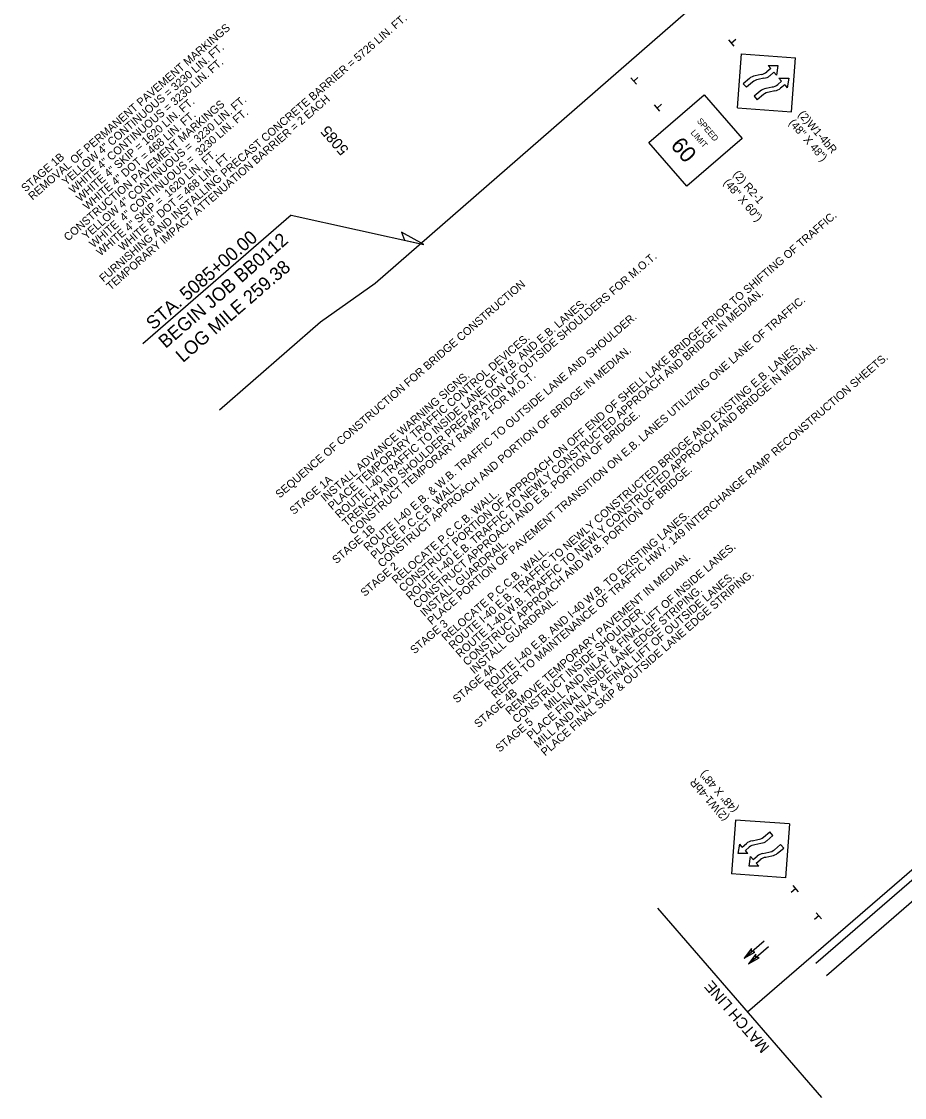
# Model space of a CAD drawing. Extents: x 259983 to 267998, y 211467 to 219827.
# Drawn here: x 259983 to 261307, y 216506 to 218119 of the extents above; entities that cross this region are included whole.
import ezdxf

# ---------------------------------------------------------------- set-up
doc = ezdxf.new("R2010")
doc.units = 0
for name, color, linetype in [('Default', 7, 'Continuous'), ('Level 24', 7, 'Continuous'), ('Level 43', 7, 'Continuous'), ('Level 58', 7, 'Continuous'), ('Level 59', 7, 'Continuous'), ('R-W - CofA', 7, 'Continuous'), ('R_MOT', 7, 'Continuous'), ('R_MOT STAGE 1', 7, 'Continuous'), ('R_MOT STAGE 2', 7, 'Continuous'), ('ROAD', 7, 'Continuous'), ('STATIONING1', 7, 'Continuous')]:
    doc.layers.add(name, color=color, linetype=linetype)

msp = doc.modelspace()

# ---------------------------------------------------------------- linework, layer by layer
at = {"layer": 'Level 24'}
for points in [[(260387.1, 217828.4), (260164.4, 217635.7)], [(260387.1, 217828.4), (260585.8, 217784.8)]]:
    msp.add_lwpolyline(points, dxfattribs=at)
at = {"layer": 'Level 43'}
for points in [[(261066, 216714.9), (261096, 216740.8)], [(261072.6, 216706.1), (261102.6, 216732.1)]]:
    msp.add_lwpolyline(points, dxfattribs=at)
at = {"layer": 'Level 58'}
for points in [[(261077.2, 216729.5), (261066, 216714.9), (261082.1, 216723.8), (261077.4, 216724.7)], [(261083.7, 216720.8), (261072.6, 216706.1), (261088.6, 216715.1), (261083.9, 216716)]]:
    msp.add_lwpolyline(points, close=True, dxfattribs=at)
at = {"layer": 'Level 59'}
msp.add_lwpolyline([(260557.1, 217791), (260585.8, 217784.8), (260552.6, 217802.9)], close=True, dxfattribs=at)
at = {"layer": 'R-W - CofA'}
msp.add_lwpolyline([(260279.4, 217536.6), (260430.8, 217668.5), (260512.8, 217726.6), (260994.1, 218146)], dxfattribs=at)
at = {"layer": 'R_MOT'}
for p, q in [((261051, 218082.1), (261043, 218091.4)), ((261047, 218086.7), (261053.5, 218092.3)), ((261056.4, 217989.4), (261062.2, 218070.3)), ((261062.2, 218070.3), (261143, 218064.4)), ((261102, 218052.9), (261116.6, 218053)), ((261102, 218052.9), (261105.9, 218048.4)), ((261116.6, 218053), (261114.5, 218038.5)), ((261137.1, 217983.7), (261143, 218064.4)), ((260904.5, 218025.1), (260896.4, 218034.3)), ((260900.5, 218029.7), (260906.9, 218035.2)), ((261074, 218033.6), (261064.9, 218025.7)), ((261091.7, 218039.4), (261082.6, 218037.3)), ((261095.9, 218033.9), (261087.3, 218031.9)), ((261105.9, 218048.4), (261100.2, 218043.4)), ((261110.6, 218043), (261104.4, 218037.7)), ((261110.6, 218043), (261114.5, 218038.5)), ((261118.3, 218034), (261133, 218034.1)), ((261118.3, 218034), (261122.2, 218029.6)), ((261133, 218034.1), (261130.8, 218019.7)), ((261064.9, 218025.7), (261069.6, 218020.3)), ((261078.7, 218028.2), (261069.6, 218020.3)), ((261108, 218020.6), (261099, 218018.4)), ((261122.2, 218029.6), (261116.5, 218024.6)), ((261126.9, 218024.2), (261120.7, 218018.8)), ((261126.9, 218024.2), (261130.8, 218019.7)), ((261090.4, 218014.7), (261081.2, 218006.8)), ((261081.2, 218006.8), (261085.9, 218001.4)), ((261095, 218009.3), (261085.9, 218001.4)), ((261112.2, 218015.1), (261103.6, 218013)), ((260939.5, 217984.6), (260931.5, 217993.8)), ((260935.5, 217989.2), (260942, 217994.8)), ((261056.4, 217989.4), (261137.1, 217983.7)), ((261053.1, 216921.9), (261047.3, 216841.2)), ((261133.9, 216916.2), (261053.1, 216921.9)), ((261095.3, 216896.3), (261104.4, 216904.2)), ((261109, 216898.8), (261104.4, 216904.2)), ((261133.9, 216916.2), (261128.1, 216835.3)), ((261078.1, 216890.5), (261086.7, 216892.6)), ((261099.9, 216890.9), (261109, 216898.8)), ((261057.3, 216871.5), (261059.5, 216885.9)), ((261071.9, 216871.6), (261057.3, 216871.5)), ((261063.4, 216881.4), (261059.5, 216885.9)), ((261063.4, 216881.4), (261069.5, 216886.8)), ((261068, 216876), (261073.8, 216881)), ((261071.9, 216871.6), (261068, 216876)), ((261082.3, 216885), (261091.3, 216887.2)), ((261094.4, 216871.7), (261103, 216873.7)), ((261111.6, 216877.4), (261120.7, 216885.3)), ((261116.2, 216872), (261125.4, 216879.9)), ((261125.4, 216879.9), (261120.7, 216885.3)), ((261073.6, 216852.6), (261075.8, 216867.1)), ((261079.7, 216862.6), (261075.8, 216867.1)), ((261079.7, 216862.6), (261085.9, 216867.9)), ((261084.4, 216857.2), (261090.1, 216862.2)), ((261088.3, 216852.7), (261084.4, 216857.2)), ((261098.6, 216866.2), (261107.6, 216868.3)), ((261128.1, 216835.3), (261047.3, 216841.2)), ((261088.3, 216852.7), (261073.6, 216852.6)), ((261139.2, 216823.5), (261147.3, 216814.2)), ((261143.2, 216818.9), (261136.8, 216813.3)), ((261178.3, 216778.4), (261171.8, 216772.8)), ((261174.3, 216783), (261182.3, 216773.7))]:
    msp.add_line(p, q, dxfattribs=at)
msp.add_lwpolyline([(261063.1, 217943.5), (260980.3, 217871.9), (260923.4, 217937.6), (261006.3, 218009.2)], close=True, dxfattribs=at)
for centre, major_axis in [((261085.9, 218020.4), (-11.6, 13.4)), ((261088.3, 218056.6), (11.6, -13.4)), ((261092.5, 218050.8), (11.6, -13.4)), ((261090.6, 218015), (-11.6, 13.4)), ((261102.2, 218001.5), (-11.6, 13.4)), ((261104.6, 218037.7), (11.6, -13.4)), ((261108.9, 218032), (11.6, -13.4)), ((261106.9, 217996.1), (-11.6, 13.4)), ((261081.4, 216873.6), (-11.6, 13.4)), ((261083.3, 216909.5), (11.6, -13.4)), ((261088, 216904), (11.6, -13.4)), ((261085.7, 216867.9), (-11.6, 13.4)), ((261097.7, 216854.7), (-11.6, 13.4)), ((261099.6, 216890.6), (11.6, -13.4)), ((261104.4, 216885.2), (11.6, -13.4)), ((261102, 216849), (-11.6, 13.4))]:
    msp.add_ellipse(centre, major_axis=major_axis, ratio=0.9, start_param=5.717125, end_param=6.306311, dxfattribs=at)
at = {"layer": 'R_MOT STAGE 1'}
for p, q in [((261173.7, 216707.1), (261504.2, 216993.2)), ((261189.4, 216688.9), (261519.9, 216975)), ((261182.4, 216506), (260936.7, 216789.8))]:
    msp.add_line(p, q, dxfattribs=at)
at = {"layer": 'R_MOT STAGE 2'}
msp.add_line((261071.3, 216634.3), (261479, 216987.2), dxfattribs=at)

# ---------------------------------------------------------------- texts
at = {"layer": 'Default'}
for s, p in [('REMOVAL OF PERMANENT PAVEMENT MARKINGS', (259999.2, 217850.4)), ('FURNISHING AND INSTALLING PRECAST CONCRETE BARRIER = 5726 LIN. FT.', (260105.6, 217727.5)), (' YELLOW 4" CONTINUOUS = 3230 LIN. FT.', (260046.1, 217869.6)), (' WHITE 4" CONTINUOUS = 3230 LIN. FT.', (260056.8, 217857.3)), ('CONSTRUCTION PAVEMENT MARKINGS', (260052.4, 217789)), (' WHITE 4" SKIP = 1620 LIN. FT.', (260067.4, 217845)), ('     YELLOW 4" CONTINUOUS =  3230 LIN. FT.', (260063, 217776.7)), ('TEMPORARY IMPACT ATTENUATION BARRIER = 2 EACH', (260116.2, 217715.3)), ('     WHITE  4" CONTINUOUS =  3230 LIN. FT.', (260073.7, 217764.4)), (' WHITE 4" DOT = 468 LIN. FT.', (260078, 217832.7)), ('STAGE 1B', (259988.6, 217862.7)), ('     WHITE 4" SKIP =  1620 LIN. FT.', (260084.3, 217752.1)), (' WHITE 8" DOT = 468 LIN. FT.', (260131.2, 217771.3))]:
    msp.add_text(s, height=12, rotation=40.8833, dxfattribs=at).set_placement(p)
at = {"layer": 'Level 24'}
for s, p in [('STA. 5085+00.00', (260180.1, 217655.5)), ('BEGIN JOB BB0112', (260198.7, 217628)), ('LOG MILE 259.38', (260224.6, 217606.7))]:
    msp.add_text(s, height=20, rotation=40.8833, dxfattribs=at).set_placement(p)
at = {"layer": 'R_MOT'}
for s, height, rotation, p in [('(2)W1-4bR', 12, 310.8833, (261146.3, 217979.2)), ('SPEED', 9.05, 310.8555, (260994.8, 217969.4)), ('(48" X 48")', 12, 310.8833, (261132.3, 217966.5)), ('LIMIT', 9.05, 310.8555, (260985.2, 217951.9)), ('60', 24.26, 310.8555, (260954.6, 217932.4)), ('(2) R2-1', 12.13, 310.8555, (261048.8, 217889.5)), ('(48" X 60")', 12.129, 310.8555, (261034.3, 217877)), ('(2)W1-4bR', 12, 130.8833, (261044, 216926.3)), ('(48" X 48")', 12, 130.8833, (261058, 216939.1))]:
    msp.add_text(s, height=height, rotation=rotation, dxfattribs=at).set_placement(p)
at = {"layer": 'ROAD'}
for s, p in [('CONSTRUCT PORTION OF APPROACH ON OFF END OF SHELL LAKE BRIDGE PRIOR TO SHIFTING OF TRAFFIC.', (260554.9, 217263)), ('TRENCH AND SHOULDER PREPARATION OF OUTSIDE SHOULDERS FOR M.O.T.', (260469.8, 217361.3)), ('SEQUENCE OF CONSTRUCTION FOR BRIDGE CONSTRUCTION', (260369.7, 217403.6)), ('ROUTE I-40 E.B. TRAFFIC TO NEWLY CONSTRUCTED APPROACH AND BRIDGE IN MEDIAN.', (260565.5, 217250.7)), ('ROUTE I-40 TRAFFIC TO INSIDE LANE OF W.B. AND E.B. LANES.', (260459.1, 217373.6)), ('PLACE PORTION OF PAVEMENT TRANSITION ON E.B. LANES UTILIZING ONE LANE OF TRAFFIC.', (260597.5, 217213.8)), ('ROUTE I-40 E.B. & W.B. TRAFFIC TO OUTSIDE LANE AND SHOULDER.', (260501.7, 217324.4)), ('PLACE TEMPORARY TRAFFIC CONTROL DEVICES.', (260448.5, 217385.9)), ('CONSTRUCT APPROACH AND PORTION OF BRIDGE IN MEDIAN.', (260523, 217299.9)), ('ROUTE I-40 E.B. TRAFFIC TO NEWLY CONSTRUCTED BRIDGE AND EXISTING E.B. LANES.', (260629.4, 217177)), ('ROUTE 1-40 W.B. TRAFFIC TO NEWLY CONSTRUCTED APPROACH AND BRIDGE IN MEDIAN.', (260640, 217164.7)), ('REFER TO MAINTENANCE OF TRAFFIC HWY. 149 INTERCHANGE RAMP RECONSTRUCTION SHEETS.', (260693.2, 217103.2)), ('INSTALL ADVANCE WARNING SIGNS.', (260437.9, 217398.2)), ('CONSTRUCT TEMPORARY RAMP 2 FOR M.O.T.', (260480.4, 217349)), ('CONSTRUCT APPROACH AND E.B. PORTION OF BRIDGE.', (260576.2, 217238.4)), ('STAGE 1A', (260390.9, 217379)), ('CONSTRUCT APPROACH AND W.B. PORTION OF BRIDGE.', (260650.7, 217152.4)), ('PLACE P.C.C.B. WALL.', (260512.3, 217312.1)), ('RELOCATE P.C.C.B. WALL.', (260544.3, 217275.3)), ('ROUTE I-40 E.B. AND I-40 W.B. TO EXISTING LANES.', (260682.6, 217115.5)), ('STAGE 1B', (260454.8, 217305.3)), ('INSTALL GUARDRAIL.', (260586.8, 217226.1)), ('RELOCATE P.C.C.B. WALL.', (260618.7, 217189.3)), ('MILL AND INLAY & FINAL LIFT OF INSIDE LANES.', (260772.1, 217085.5)), ('STAGE 2', (260497.3, 217256.2)), ('REMOVE TEMPORARY PAVEMENT IN MEDIAN.', (260714.5, 217078.6)), ('PLACE FINAL SKIP & OUTSIDE LANE EDGE STRIPING.', (260767.7, 217017.2)), ('MILL AND INLAY & FINAL LIFT OF OUTSIDE LANES.', (260757, 217029.5)), ('PLACE FINAL INSIDE LANE EDGE STRIPING.', (260746.4, 217041.8)), ('INSTALL GUARDRAIL.', (260661.3, 217140.1)), ('CONSTRUCT INSIDE SHOULDER.', (260725.1, 217066.4)), ('STAGE 3', (260571.8, 217170.1)), ('STAGE 4A', (260635.6, 217096.4)), ('STAGE 4B', (260667.6, 217059.5)), ('STAGE 5', (260699.5, 217022.7))]:
    msp.add_text(s, height=12, rotation=40.8833, dxfattribs=at).set_placement(p)
at = {"layer": 'STATIONING1'}
for s, p in [('5085', (260474.3, 217927.3)), ('MATCH LINE', (261105.1, 216581.7))]:
    msp.add_text(s, height=16.5, rotation=130.8833, dxfattribs=at).set_placement(p)

doc.saveas('drawing.dxf')
